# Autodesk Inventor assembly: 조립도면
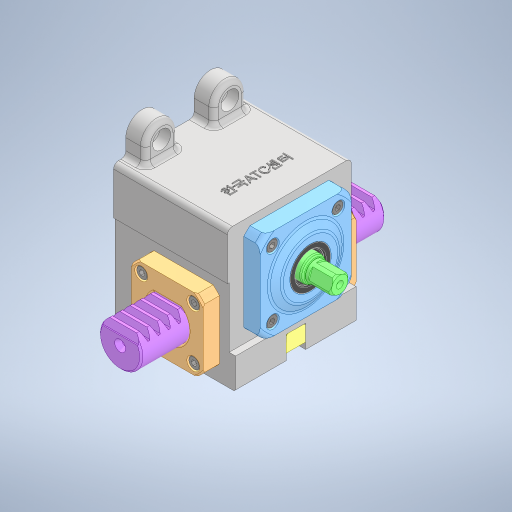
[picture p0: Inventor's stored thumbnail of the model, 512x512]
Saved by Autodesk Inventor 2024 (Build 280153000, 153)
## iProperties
Created: 2024-11
Part Number: 조립도면
Document SubType Name: Assembly
Designer: user
Author: user
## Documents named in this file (10)
- C:\Users\user\Desktop\741104V1003\조립도면.iam
- C:\Users\user\Desktop\741104V1003\본체.ipt
- C:\Users\user\Desktop\741104V1003\깊음 홈 볼 베어링 6202\깊음 홈 볼 베어링 6202.ipt
- C:\Users\user\Desktop\741104V1003\피니언 축\피니언 축.ipt
- C:\Users\user\Desktop\741104V1003\커버\커버.ipt
- C:\Users\user\Desktop\741104V1003\육각 소켓 머리 볼트 M4x10\육각 소켓 머리 볼트 M4x10.ipt
- C:\Users\user\Desktop\741104V1003\수지 부시\수지 부시.ipt
- C:\Users\user\Desktop\741104V1003\래크\래크.ipt
- C:\Users\user\Desktop\741104V1003\스톱퍼\스톱퍼.ipt
- C:\Users\user\Desktop\741104V1003\오일 실 15 25 4\오일 실 15 25 4.ipt
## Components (1 placed, 1 different names)
1. 피니언 축:1
